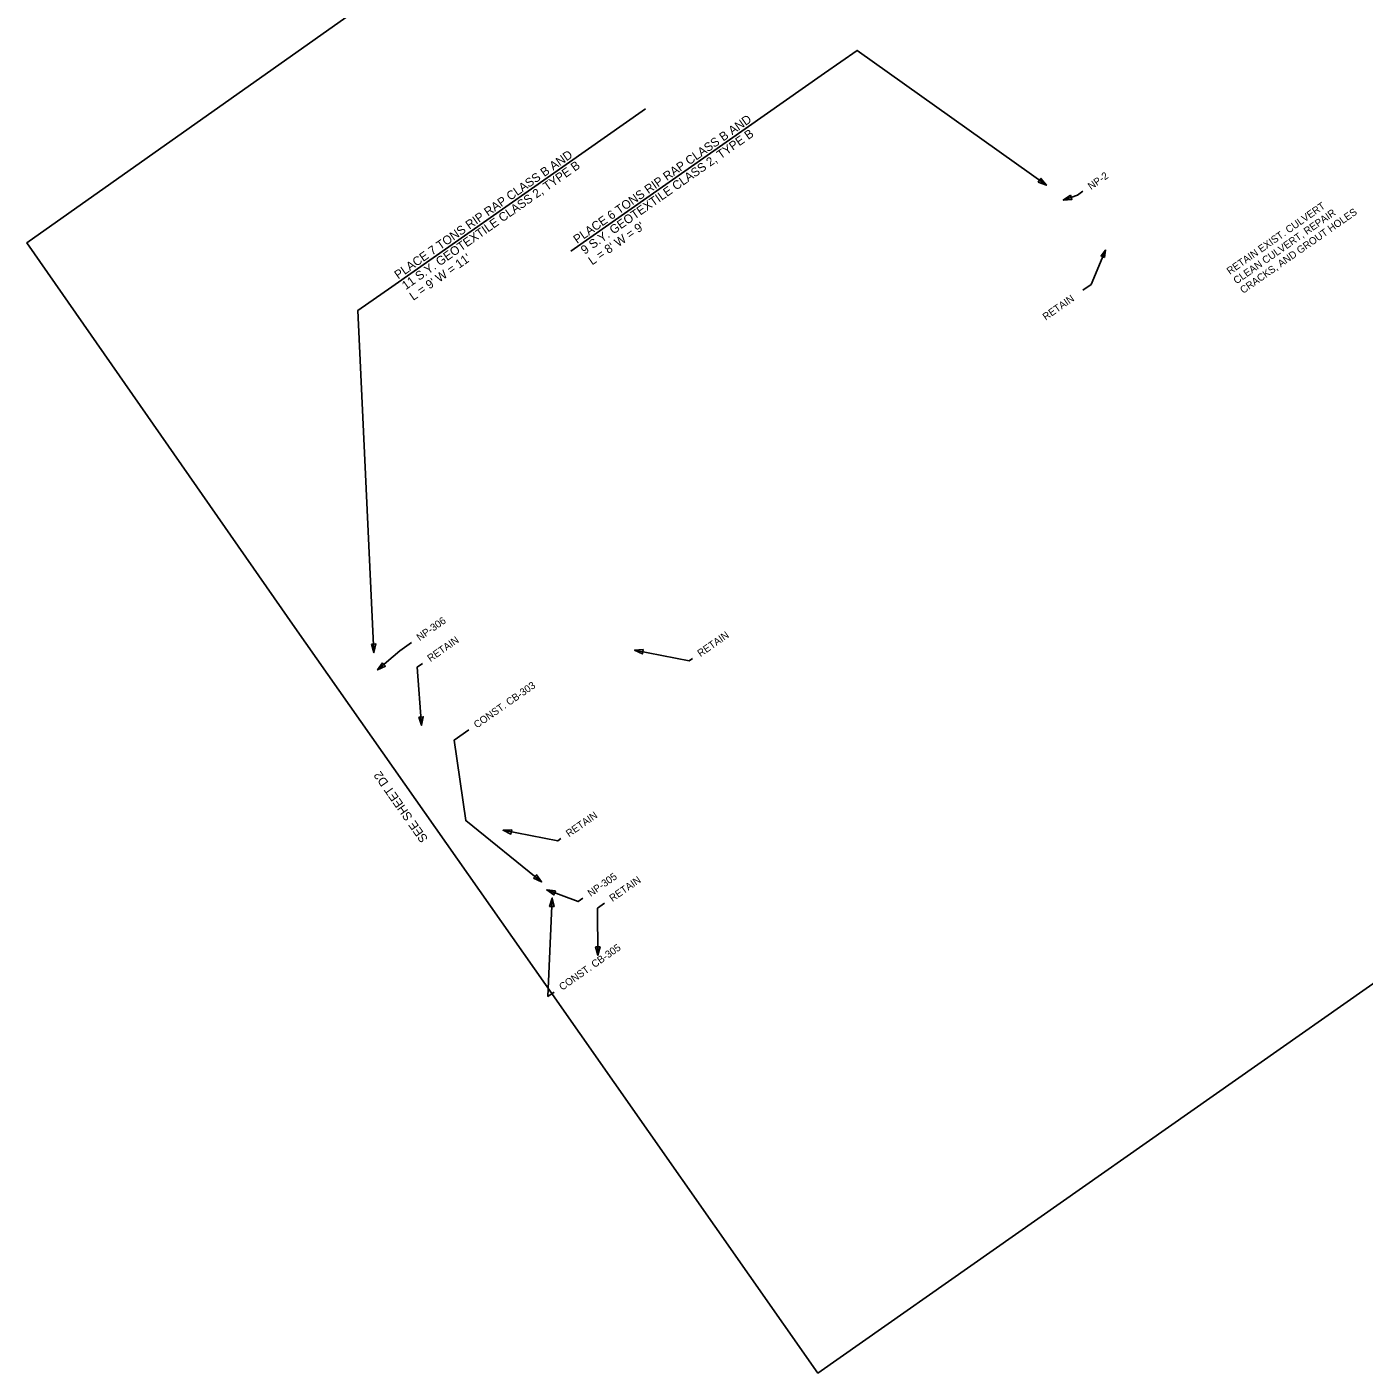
# Model space of a CAD drawing. Extents: x 1605049 to 1606865, y 1089598 to 1091250.
# Drawn here: x 1605049 to 1605969, y 1089598 to 1090524 of the extents above; entities that cross this region are included whole.
import ezdxf

# ---------------------------------------------------------------- set-up
doc = ezdxf.new("R2010")
doc.units = 0
for name, color, linetype in [('Plan_Clip', 7, 'Continuous'), ('RD_SHT_MatchLine', 7, 'Continuous'), ('RD_TX_Drainage', 7, 'Continuous')]:
    doc.layers.add(name, color=color, linetype=linetype)

msp = doc.modelspace()

# ---------------------------------------------------------------- linework, layer by layer
at = {"layer": 'Plan_Clip'}
msp.add_lwpolyline([(1605233.56, 1090111.04), (1605405.83, 1089865.44), (1605593.12, 1089598.42), (1606815.94, 1090456.14), (1606682.28, 1090657.78), (1606533.03, 1090870.55), (1606535.89, 1090871.82), (1606406.67, 1091049.1), (1606294.17, 1091212.27), (1606168.16, 1091123.23), (1606148, 1091151.76), (1605049.41, 1090375.46)], close=True, dxfattribs=at)
msp.add_lwpolyline([(1605233.56, 1090111.04), (1605405.83, 1089865.44), (1605593.12, 1089598.42), (1606815.94, 1090456.14), (1606682.28, 1090657.78), (1606533.03, 1090870.55), (1606535.89, 1090871.82), (1606406.67, 1091049.1), (1606294.17, 1091212.27), (1606168.16, 1091123.23), (1606148, 1091151.76), (1605049.41, 1090375.46)], close=True, dxfattribs=at)
msp.add_lwpolyline([(1605233.56, 1090111.04), (1605405.83, 1089865.44), (1605593.12, 1089598.42), (1606815.94, 1090456.14), (1606682.28, 1090657.78), (1606533.03, 1090870.55), (1606535.89, 1090871.82), (1606406.67, 1091049.1), (1606294.17, 1091212.27), (1606168.16, 1091123.23), (1606148, 1091151.76), (1605049.41, 1090375.46)], close=True, dxfattribs=at)
msp.add_lwpolyline([(1605233.56, 1090111.04), (1605405.83, 1089865.44), (1605593.12, 1089598.42), (1606815.94, 1090456.14), (1606682.28, 1090657.78), (1606533.03, 1090870.55), (1606535.89, 1090871.82), (1606406.67, 1091049.1), (1606294.17, 1091212.27), (1606168.16, 1091123.23), (1606148, 1091151.76), (1605049.41, 1090375.46)], close=True, dxfattribs=at)
msp.add_lwpolyline([(1605233.56, 1090111.04), (1605405.83, 1089865.44), (1605593.12, 1089598.42), (1606815.94, 1090456.14), (1606682.28, 1090657.78), (1606533.03, 1090870.55), (1606535.89, 1090871.82), (1606406.67, 1091049.1), (1606294.17, 1091212.27), (1606168.16, 1091123.23), (1606148, 1091151.76), (1605049.41, 1090375.46)], close=True, dxfattribs=at)
at = {"layer": 'RD_TX_Drainage'}
for p, q in [((1605597.71, 1090491.96), (1605423.23, 1090369.58)), ((1605474.7, 1090467.58), (1605300.22, 1090345.19))]:
    msp.add_line(p, q, dxfattribs=at)
for points in [[(1605597.71, 1090491.96), (1605620.06, 1090507.64), (1605750.21, 1090414.99)], [(1605775.34, 1090410.78), (1605771.69, 1090408.22), (1605761.81, 1090404.75)], [(1605775.34, 1090342.82), (1605781.03, 1090346.81), (1605790.85, 1090370.34)], [(1605300.22, 1090345.19), (1605276.99, 1090328.89), (1605287.99, 1090093.74)], [(1605313.88, 1090100.66), (1605305.76, 1090094.96), (1605290.43, 1090081.79)], [(1605506.92, 1090089.7), (1605504.65, 1090088.11), (1605467.13, 1090095.39)], [(1605321.29, 1090086.28), (1605317.7, 1090083.76), (1605320.76, 1090043.75)], [(1605353.22, 1090040.59), (1605343.18, 1090033.55), (1605351.02, 1089978.26), (1605403.14, 1089936.08)], [(1605416.54, 1089965.83), (1605414.27, 1089964.24), (1605376.74, 1089971.52)], [(1605431.52, 1089924.82), (1605428.32, 1089922.58), (1605406.79, 1089930.57)], [(1605411.88, 1089860.36), (1605407.56, 1089857.33), (1605410.52, 1089924.92)], [(1605446.39, 1089921.36), (1605441.55, 1089917.97), (1605441.91, 1089885.68)]]:
    msp.add_lwpolyline(points, dxfattribs=at)
for points in [[(1605744.59, 1090417.09), (1605750.21, 1090414.99), (1605746.39, 1090419.62)], [(1605766.76, 1090408.13), (1605761.81, 1090404.75), (1605767.79, 1090405.2)], [(1605790.19, 1090365.38), (1605790.85, 1090370.34), (1605787.8, 1090366.38)], [(1605286.17, 1090099.45), (1605287.99, 1090093.74), (1605289.27, 1090099.6)], [(1605473.12, 1090095.81), (1605467.13, 1090095.39), (1605472.52, 1090092.76)], [(1605293.82, 1090086.75), (1605290.43, 1090081.79), (1605295.84, 1090084.39)], [(1605318.77, 1090049.41), (1605320.76, 1090043.75), (1605321.86, 1090049.64)], [(1605382.73, 1089971.94), (1605376.74, 1089971.52), (1605382.14, 1089968.89)], [(1605397.66, 1089938.52), (1605403.14, 1089936.08), (1605399.62, 1089940.93)], [(1605412.76, 1089930.01), (1605406.79, 1089930.57), (1605411.68, 1089927.1)], [(1605411.82, 1089919.06), (1605410.52, 1089924.92), (1605408.72, 1089919.2)], [(1605440.29, 1089891.46), (1605441.91, 1089885.68), (1605443.4, 1089891.49)]]:
    msp.add_lwpolyline(points, close=True, dxfattribs=at)

# ---------------------------------------------------------------- texts
at = {"layer": 'RD_SHT_MatchLine'}
msp.add_text('SEE SHEET D2', height=6, rotation=125.0981, dxfattribs=at).set_placement((1605325.37, 1089965.69))
at = {"layer": 'RD_TX_Drainage'}
for s, height, p in [('PLACE 6 TONS RIP RAP CLASS B AND', 6, (1605427.65, 1090374.51)), ('9 S.Y. GEOTEXTILE CLASS 2, TYPE B', 6, (1605432.82, 1090367.14)), ('PLACE 7 TONS RIP RAP CLASS B AND', 6, (1605304.64, 1090350.12)), ('11 S.Y. GEOTEXTILE CLASS 2, TYPE B', 6, (1605309.81, 1090342.75)), ('NP-2', 5, (1605780.87, 1090411.61)), ('RETAIN EXIST. CULVERT', 5, (1605876.34, 1090353.3)), ('CLEAN CULVERT, REPAIR', 5, (1605880.93, 1090346.75)), ('CRACKS, AND GROUT HOLES', 5, (1605885.52, 1090340.2)), ("L = 8' W = 9'", 6, (1605437.99, 1090359.77)), ("L = 9' W = 11'", 6, (1605314.98, 1090335.39)), ('RETAIN', 5, (1605749.8, 1090321.85)), ('NP-306', 5, (1605319.41, 1090101.49)), ('RETAIN', 5, (1605326.82, 1090087.1)), ('RETAIN', 5, (1605512.45, 1090090.53)), ('CONST. CB-303', 5, (1605358.75, 1090041.42)), ('RETAIN', 5, (1605422.07, 1089966.66)), ('NP-305', 5, (1605437.04, 1089925.64)), ('RETAIN', 5, (1605451.92, 1089922.19)), ('CONST. CB-305', 5, (1605417.41, 1089861.19))]:
    msp.add_text(s, height=height, rotation=35.04683, dxfattribs=at).set_placement(p)

doc.saveas('drawing.dxf')
